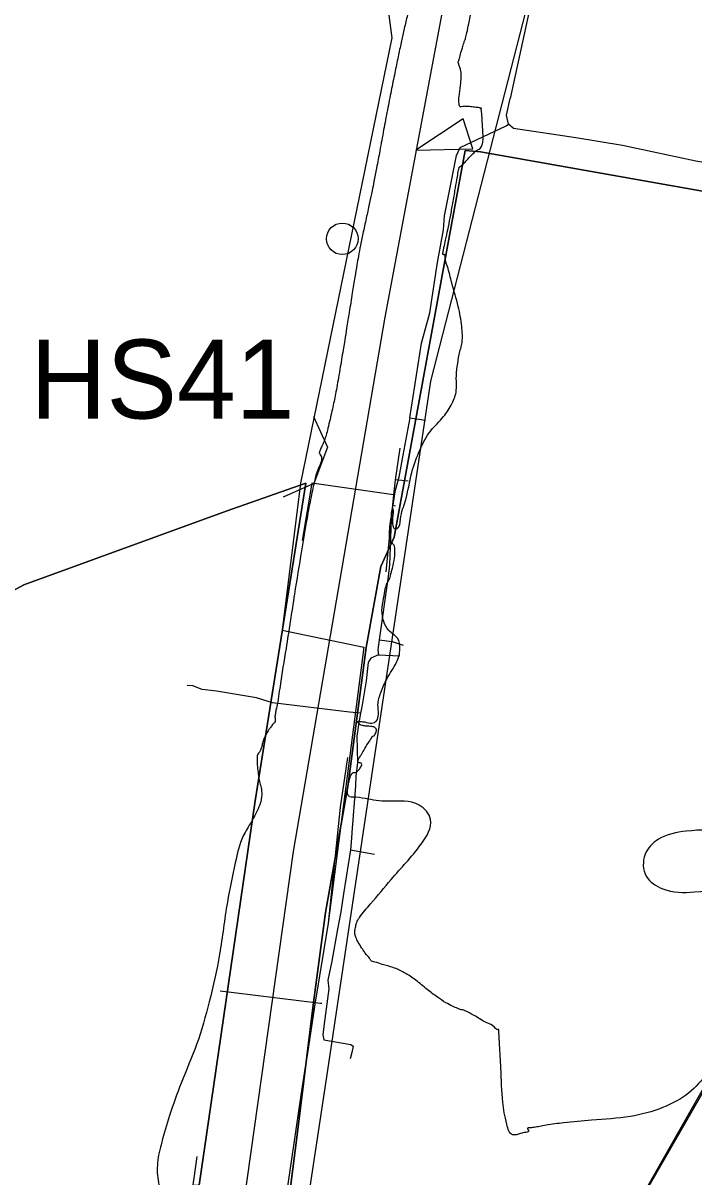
# Model space of a CAD drawing. Extents: x -478232 to -472707, y -1118753 to -1113967.
# Drawn here: x -475972.9 to -475887.9, y -1117588.2 to -1117442 of the extents above; entities that cross this region are included whole.
import ezdxf

# ---------------------------------------------------------------- set-up
doc = ezdxf.new("R2010")
doc.units = 0
for name, color, linetype in [('cesty', 7, 'Continuous'), ('hospodářské sjezdy', 7, 'Continuous'), ('nesmenovane pozemky', 7, 'Continuous'), ('ObPÚ', 7, 'Continuous'), ('plyn_stl', 7, 'Continuous'), ('silnice', 7, 'Continuous'), ('telekomunikační kabel_O2', 7, 'Continuous'), ('VAK_vodovod', 7, 'Continuous'), ('Vrstevnice_vedlejsi', 7, 'Continuous')]:
    doc.layers.add(name, color=color, linetype=linetype)

msp = doc.modelspace()

# ---------------------------------------------------------------- linework, layer by layer
at = {"layer": 'cesty'}
msp.add_line((-475915.938, -1117457.98), (-475917.133, -1117454.162), dxfattribs=at)
msp.add_lwpolyline([(-475917.133, -1117454.162), (-475923.164, -1117458.147), (-475915.938, -1117457.98)], dxfattribs=at)
msp.add_circle((-475932.467, -1117469.362), 2, dxfattribs=at)
at = {"layer": 'hospodářské sjezdy'}
for p, q in [((-475936.094, -1117491.874), (-475934.346, -1117495.765)), ((-475934.346, -1117495.765), (-475936.078, -1117500.333)), ((-475936.078, -1117500.333), (-475939.967, -1117502.085))]:
    msp.add_line(p, q, dxfattribs=at)
at = {"layer": 'nesmenovane pozemky'}
for p, q in [((-475916.88, -1117458.16), (-475919.49, -1117472.13)), ((-475919.49, -1117472.13), (-475925.88, -1117507.14)), ((-475934.6, -1117554.69), (-475936.13, -1117566.09))]:
    msp.add_line(p, q, dxfattribs=at)
for points in [[(-475951.7, -1117685.1), (-475927.26, -1117688.72), (-475918.95, -1117689.8), (-475884.78, -1117695.44), (-475871.68, -1117697.52), (-475898.5, -1117669.12), (-475903.93, -1117664.35), (-475905.71, -1117629.13), (-475906.78, -1117612.16), (-475902.49, -1117604.75), (-475882.63, -1117570.25), (-475876.2, -1117558.77), (-475871.25, -1117549.71), (-475870.12, -1117548.49), (-475868.56, -1117541.56), (-475866.64, -1117537.01), (-475865.5, -1117532.56), (-475858.35, -1117525.46), (-475844.8, -1117506.28), (-475833.86, -1117486.94), (-475831.88, -1117483.59), (-475829.4, -1117473.48), (-475914.94, -1117458.35), (-475916.88, -1117458.16)], [(-475919.49, -1117472.13), (-475916.88, -1117458.16), (-475914.94, -1117458.35), (-475829.4, -1117473.48), (-475831.88, -1117483.59), (-475833.86, -1117486.94), (-475844.8, -1117506.28), (-475858.35, -1117525.46), (-475865.5, -1117532.56), (-475866.64, -1117537.01), (-475868.56, -1117541.56), (-475870.12, -1117548.49), (-475871.25, -1117549.71), (-475876.2, -1117558.77), (-475882.63, -1117570.25), (-475902.49, -1117604.75)], [(-475940.34, -1117599.73), (-475938.19, -1117582.83), (-475936.13, -1117566.09), (-475934.6, -1117554.69), (-475931.78, -1117538.72), (-475929.43, -1117521.14), (-475927.57, -1117510.84), (-475925.88, -1117507.14), (-475919.49, -1117472.13)], [(-475937.08, -1117500.29), (-475943.5, -1117540.53), (-475950.59, -1117589.22), (-475972.84, -1117590.29), (-476004.64, -1117592.26), (-475999.55, -1117575.26), (-475994.23, -1117573.44), (-475992.2, -1117563.25), (-475986.19, -1117534.11), (-475984.93, -1117525.82), (-475982.04, -1117518.19), (-475972.81, -1117513.2), (-475947.17, -1117503.84), (-475937.08, -1117500.29)], [(-475947.17, -1117503.84), (-475972.81, -1117513.2), (-475982.04, -1117518.19), (-475984.93, -1117525.82), (-475986.19, -1117534.11), (-475992.2, -1117563.25), (-475994.23, -1117573.44), (-475999.55, -1117575.26), (-476004.64, -1117592.26), (-475972.84, -1117590.29), (-475950.59, -1117589.22), (-475943.5, -1117540.53), (-475937.08, -1117500.29), (-475947.17, -1117503.84)], [(-475925.88, -1117507.14), (-475927.57, -1117510.84), (-475929.43, -1117521.14), (-475931.78, -1117538.72), (-475934.6, -1117554.69)], [(-475936.13, -1117566.09), (-475938.19, -1117582.83), (-475940.34, -1117599.73)]]:
    msp.add_lwpolyline(points, dxfattribs=at)
at = {"layer": 'ObPÚ'}
msp.add_lwpolyline([(-475797.1, -1117434.24), (-475812.51, -1117451.24), (-475815.72, -1117464.29), (-475829.4, -1117473.48), (-475831.88, -1117483.59), (-475844.8, -1117506.28), (-475858.35, -1117525.46), (-475865.5, -1117532.56), (-475866.64, -1117537.01), (-475868.56, -1117541.56), (-475870.12, -1117548.49), (-475871.25, -1117549.71), (-475906.78, -1117612.16), (-475903.93, -1117664.35), (-475871.68, -1117697.52), (-475884.78, -1117695.44), (-475927.26, -1117688.72), (-475927.26, -1117688.72), (-475951.7, -1117685.1), (-475955.15, -1117684.42), (-475964.23, -1117682.64), (-475976.69, -1117679.99)], dxfattribs=at)
at = {"layer": 'plyn_stl'}
for p, q in [((-475925.98, -1117501.775), (-475926.943, -1117511.519)), ((-475947.94, -1117564.611), (-475946.213, -1117564.822)), ((-475946.213, -1117564.822), (-475935.234, -1117566.161)), ((-475935.234, -1117566.161), (-475935.062, -1117566.182))]:
    msp.add_line(p, q, dxfattribs=at)
for points in [[(-475925.179, -1117495.887), (-475925.776, -1117499.864), (-475925.98, -1117501.775), (-475927.156, -1117501.607), (-475936.338, -1117500.287), (-475937.535, -1117507.551)], [(-475924.115, -1117500.041), (-475924.12, -1117500.04), (-475924.5, -1117500), (-475925.776, -1117499.864)], [(-475950.891, -1117585.581), (-475951.277, -1117588.32), (-475951.277, -1117588.32), (-475952.244, -1117594.708), (-475952.569, -1117598.534), (-475951.885, -1117598.735), (-475939.635, -1117602.325), (-475939.681, -1117602.62), (-475941.682, -1117615.413), (-475944.166, -1117633.413), (-475944.166, -1117633.413), (-475944.769, -1117640.016), (-475945.933, -1117645.497), (-475946.953, -1117652.292), (-475950.061, -1117674.019), (-475950.384, -1117679.114), (-475952.306, -1117682.652), (-475953.329, -1117685.537), (-475953.931, -1117690.234), (-475955.586, -1117703.027), (-475955.894, -1117706.481)]]:
    msp.add_lwpolyline(points, dxfattribs=at)
at = {"layer": 'silnice'}
msp.add_lwpolyline([(-475957.898, -1117684.778), (-475949.882, -1117626.621), (-475938.626, -1117546.976), (-475927.029, -1117479.269), (-475917.649, -1117429.299), (-475903.982, -1117378.322)], dxfattribs=at)
at = {"layer": 'telekomunikační kabel_O2'}
for points in [[(-475967.4, -1117098.97), (-475940.43, -1117167.78), (-475950.06, -1117174), (-475931.33, -1117228.82), (-475924.1, -1117281.32), (-475911.23, -1117358.65), (-475927.92, -1117430.83), (-475926.17, -1117443.9), (-475937.75, -1117500.32), (-475940.1, -1117518.94), (-475929.72, -1117521.06), (-475934.27, -1117556.02), (-475935.89, -1117566.02), (-475936.969, -1117573.032)], [(-475891.45, -1117356.54), (-475891.64, -1117357.2), (-475890.45, -1117362.41), (-475889.23, -1117368.48), (-475890.21, -1117370.93), (-475900.63, -1117410.24), (-475907.44, -1117434.27), (-475911.21, -1117451.58)], [(-475911.41, -1117454.83), (-475911.67, -1117453.71), (-475911.21, -1117451.58)], [(-475923.91, -1117492.02), (-475922.43, -1117482.59), (-475921.39, -1117478.74), (-475920.39, -1117472.37), (-475919.64, -1117468.22), (-475919.5, -1117466.47), (-475918.95, -1117463.72), (-475918, -1117458.79), (-475917.51, -1117457.78), (-475911.68, -1117455.04), (-475911.41, -1117454.83)], [(-475866.596, -1117463.609), (-475871.46, -1117462.74), (-475878.05, -1117461.1), (-475887.67, -1117459.53), (-475896.96, -1117457.53), (-475902.86, -1117456.57), (-475910.78, -1117455.39), (-475911.41, -1117454.83)], [(-475923.91, -1117492.02), (-475924.79, -1117496.76), (-475925.31, -1117499.54), (-475925.81, -1117501.42), (-475926.04, -1117503.08)], [(-475923.91, -1117492.02), (-475921.9, -1117492.32)], [(-475926.04, -1117503.08), (-475926.26, -1117504.12), (-475926.26, -1117504.92), (-475926.36, -1117507.25), (-475926.48, -1117510.66), (-475926.65, -1117512.14), (-475927.78, -1117520.16)], [(-475926.04, -1117503.08), (-475925.78, -1117503.17)], [(-475927.78, -1117520.16), (-475927.97, -1117521.4), (-475927.89, -1117522.04)], [(-475927.78, -1117520.16), (-475926.14, -1117520.38), (-475924.73, -1117520.81)], [(-475927.89, -1117522.04), (-475928.86, -1117522.49), (-475929.19, -1117523.03), (-475929.45, -1117525.32), (-475929.97, -1117528.65), (-475930.16, -1117529.45)], [(-475927.89, -1117522.04), (-475925.19, -1117522.16)], [(-475930.16, -1117529.45), (-475931.57, -1117529.33), (-475941.31, -1117528.12), (-475943.33, -1117527.48), (-475948.39, -1117526.66), (-475950.2, -1117526.42), (-475951.4, -1117525.97), (-475952.12, -1117525.92)], [(-475930.16, -1117529.45), (-475930.43, -1117530.9), (-475930.6, -1117532.33), (-475930.55, -1117535.71), (-475930.75, -1117537.38), (-475930.78, -1117538.62), (-475931.26, -1117544.56), (-475931.29, -1117545.26), (-475931.44, -1117546.73)], [(-475931.82, -1117535.04), (-475932.74, -1117541.33), (-475934.27, -1117556.02), (-475935.89, -1117566.02), (-475937.71, -1117577.81), (-475938.91, -1117585.91), (-475941.61, -1117604.26), (-475944.33, -1117624.51)], [(-475931.44, -1117546.73), (-475932.33, -1117552.33), (-475932.65, -1117554.6), (-475933.06, -1117556.79), (-475933.78, -1117560.85), (-475934.28, -1117563.23), (-475934.17, -1117564.33), (-475934.76, -1117568.78), (-475934.91, -1117570.19), (-475934.8, -1117570.81), (-475931.38, -1117571.38), (-475931.07, -1117571.61), (-475931.27, -1117572.4), (-475931.48, -1117573.22)], [(-475931.44, -1117546.73), (-475928.4, -1117547.31)]]:
    msp.add_lwpolyline(points, dxfattribs=at)
at = {"layer": 'VAK_vodovod'}
msp.add_lwpolyline([(-475961.022, -1117076.006), (-475947.88, -1117107.78), (-475947.26, -1117108.989), (-475886.863, -1117255.251), (-475879.338, -1117287.714), (-475878.218, -1117296.341), (-475877.862, -1117316.562), (-475878.829, -1117320.819), (-475879.236, -1117324.31), (-475879.403, -1117324.54), (-475921.268, -1117487.378), (-475934.347, -1117574.649), (-475937.667, -1117596.666), (-475938.465, -1117600.746), (-475938.582, -1117601.233), (-475938.757, -1117601.897), (-475940.979, -1117601.583)], dxfattribs=at)
at = {"layer": 'Vrstevnice_vedlejsi'}
for points in [[(-475916.975, -1117444.292), (-475916.91, -1117444.15), (-475916.838, -1117443.929), (-475916.758, -1117443.629), (-475916.67, -1117443.25), (-475916.443, -1117442.153), (-475916.077, -1117440.337), (-475915.571, -1117437.802), (-475915.215, -1117436.045), (-475915.01, -1117435.066), (-475914.956, -1117434.864), (-475914.76, -1117434.04), (-475914.422, -1117432.594), (-475913.943, -1117430.524), (-475913.61, -1117429.082), (-475913.424, -1117428.266), (-475913.385, -1117428.077), (-475913.184, -1117427.193), (-475912.819, -1117425.614), (-475912.291, -1117423.339), (-475911.931, -1117421.787), (-475911.737, -1117420.958), (-475911.711, -1117420.852), (-475911.47, -1117419.881), (-475911.014, -1117418.045), (-475910.343, -1117415.344), (-475909.896, -1117413.541), (-475909.671, -1117412.636), (-475909.669, -1117412.628), (-475909.667, -1117412.619), (-475909.664, -1117412.607), (-475909.661, -1117412.594), (-475909.477, -1117411.965), (-475909.111, -1117410.721), (-475908.564, -1117408.862), (-475908.198, -1117407.614), (-475908.011, -1117406.977), (-475908.005, -1117406.952), (-475908, -1117406.932), (-475907.996, -1117406.917), (-475907.995, -1117406.907), (-475907.754, -1117405.931), (-475907.275, -1117403.988), (-475906.557, -1117401.079), (-475905.997, -1117398.788), (-475905.596, -1117397.117), (-475905.352, -1117396.064), (-475905.125, -1117395.027), (-475904.914, -1117394.006), (-475904.721, -1117393.002), (-475904.431, -1117391.559), (-475904.045, -1117389.677), (-475903.563, -1117387.357), (-475903.25, -1117385.773), (-475903.106, -1117384.926), (-475903.131, -1117384.815), (-475903.261, -1117384.756), (-475903.497, -1117384.749), (-475903.839, -1117384.794), (-475904.936, -1117385.955), (-475906.789, -1117388.231), (-475909.397, -1117391.622), (-475911.147, -1117393.894), (-475912.039, -1117395.047), (-475912.072, -1117395.08), (-475912.108, -1117395.141), (-475912.145, -1117395.227), (-475912.185, -1117395.34), (-475912.276, -1117395.491), (-475912.417, -1117395.68), (-475912.611, -1117395.908), (-475913.012, -1117397.232), (-475913.622, -1117399.653), (-475914.441, -1117403.172), (-475915.248, -1117406.458), (-475916.043, -1117409.512), (-475916.828, -1117412.333), (-475917.46, -1117414.614), (-475917.94, -1117416.353), (-475918.268, -1117417.552), (-475918.666, -1117419.012), (-475919.134, -1117420.732), (-475919.673, -1117422.713), (-475920.196, -1117424.706), (-475920.704, -1117426.711), (-475921.195, -1117428.727), (-475921.645, -1117430.593), (-475922.054, -1117432.306), (-475922.421, -1117433.869), (-475922.836, -1117435.571), (-475923.299, -1117437.415), (-475923.809, -1117439.399), (-475924.263, -1117441.241), (-475924.661, -1117442.942), (-475925.002, -1117444.501), (-475925.384, -1117446.3), (-475925.807, -1117448.34)], [(-475926.806, -1117512.989), (-475926.594, -1117512.679), (-475926.364, -1117512.04), (-475926.115, -1117511.073), (-475925.848, -1117509.779), (-475925.79, -1117508.798), (-475925.942, -1117508.13), (-475926.304, -1117507.777), (-475926.467, -1117507.007), (-475926.43, -1117505.822), (-475926.193, -1117504.22), (-475926.061, -1117503.535), (-475926.032, -1117503.767), (-475926.107, -1117504.915), (-475926.054, -1117505.677), (-475925.872, -1117506.054), (-475925.562, -1117506.044), (-475925.091, -1117504.861), (-475924.459, -1117502.506), (-475923.667, -1117498.977), (-475922.599, -1117496.031), (-475921.256, -1117493.667), (-475919.639, -1117491.885), (-475918.56, -1117490.191), (-475918.018, -1117488.587), (-475918.015, -1117487.071), (-475917.893, -1117485.547), (-475917.653, -1117484.016), (-475917.295, -1117482.477), (-475917.333, -1117480.451), (-475917.767, -1117477.938), (-475918.596, -1117474.938), (-475919.15, -1117472.871), (-475919.428, -1117471.736), (-475919.431, -1117471.534), (-475919.47, -1117471.408), (-475919.543, -1117471.356), (-475919.652, -1117471.379), (-475919.714, -1117471.331), (-475919.728, -1117471.212), (-475919.695, -1117471.021), (-475919.578, -1117470.457), (-475919.377, -1117469.521), (-475919.091, -1117468.211), (-475918.797, -1117466.73), (-475918.495, -1117465.079), (-475918.184, -1117463.257), (-475917.954, -1117461.912), (-475917.804, -1117461.044), (-475917.736, -1117460.653), (-475917.673, -1117460.385), (-475917.615, -1117460.241), (-475917.563, -1117460.221), (-475917.503, -1117460.188), (-475917.434, -1117460.142), (-475917.357, -1117460.084), (-475917.117, -1117459.844), (-475916.715, -1117459.423), (-475916.15, -1117458.821), (-475915.694, -1117458.384), (-475915.347, -1117458.112), (-475915.11, -1117458.006), (-475914.917, -1117457.811), (-475914.77, -1117457.525), (-475914.668, -1117457.15), (-475914.632, -1117456.464), (-475914.662, -1117455.467), (-475914.757, -1117454.161), (-475914.82, -1117453.286), (-475914.849, -1117452.843), (-475914.845, -1117452.831), (-475914.844, -1117452.821), (-475914.845, -1117452.811), (-475914.848, -1117452.803), (-475914.854, -1117452.799), (-475914.862, -1117452.799), (-475914.872, -1117452.802), (-475915.096, -1117452.775), (-475915.535, -1117452.719), (-475916.188, -1117452.632), (-475916.735, -1117452.594), (-475917.175, -1117452.603), (-475917.509, -1117452.66), (-475917.671, -1117452.239), (-475917.659, -1117451.338), (-475917.476, -1117449.959), (-475917.402, -1117448.881), (-475917.44, -1117448.105), (-475917.587, -1117447.631), (-475917.691, -1117447.306), (-475917.752, -1117447.131), (-475917.769, -1117447.105), (-475917.697, -1117446.794), (-475917.537, -1117446.198), (-475917.288, -1117445.316), (-475917.101, -1117444.68), (-475916.975, -1117444.292)], [(-475925.807, -1117448.34), (-475926.271, -1117450.621), (-475926.743, -1117453.028), (-475927.223, -1117455.562), (-475927.71, -1117458.222), (-475928.119, -1117460.397), (-475928.448, -1117462.085), (-475928.698, -1117463.287), (-475929.008, -1117464.755), (-475929.377, -1117466.489), (-475929.805, -1117468.489), (-475930.153, -1117470.183), (-475930.42, -1117471.572), (-475930.607, -1117472.656), (-475930.864, -1117474.203), (-475931.192, -1117476.212), (-475931.591, -1117478.685), (-475931.911, -1117480.673), (-475932.154, -1117482.178), (-475932.319, -1117483.199), (-475932.507, -1117484.336), (-475932.716, -1117485.589), (-475932.947, -1117486.958), (-475933.165, -1117488.181), (-475933.369, -1117489.257), (-475933.56, -1117490.186), (-475933.776, -1117491.179), (-475934.018, -1117492.236), (-475934.284, -1117493.357), (-475934.519, -1117494.236), (-475934.723, -1117494.873), (-475934.895, -1117495.268), (-475935.041, -1117495.607), (-475935.161, -1117495.889), (-475935.254, -1117496.115), (-475935.322, -1117496.274), (-475935.366, -1117496.367), (-475935.386, -1117496.394), (-475935.348, -1117496.507), (-475935.253, -1117496.706), (-475935.101, -1117496.991), (-475935.105, -1117497.404), (-475935.264, -1117497.944), (-475935.579, -1117498.612), (-475935.962, -1117499.972), (-475936.413, -1117502.024), (-475936.932, -1117504.768), (-475937.635, -1117508.885), (-475938.521, -1117514.375), (-475939.592, -1117521.239), (-475940.344, -1117525.997), (-475940.776, -1117528.651), (-475940.89, -1117529.2), (-475940.962, -1117529.609), (-475940.994, -1117529.877), (-475940.984, -1117530.005), (-475940.975, -1117530.143), (-475940.967, -1117530.29), (-475940.96, -1117530.446), (-475940.993, -1117530.576), (-475941.066, -1117530.679), (-475941.18, -1117530.754), (-475941.378, -1117530.99), (-475941.658, -1117531.386), (-475942.021, -1117531.943), (-475942.311, -1117532.508), (-475942.528, -1117533.081), (-475942.672, -1117533.663), (-475942.827, -1117534.113), (-475942.993, -1117534.43), (-475943.171, -1117534.615), (-475943.259, -1117535.054), (-475943.258, -1117535.746), (-475943.166, -1117536.692), (-475943.05, -1117537.531), (-475942.909, -1117538.261), (-475942.742, -1117538.884), (-475942.673, -1117539.509), (-475942.701, -1117540.138), (-475942.826, -1117540.769), (-475943.252, -1117541.788), (-475943.979, -1117543.194), (-475945.007, -1117544.986), (-475946.021, -1117548.378), (-475947.023, -1117553.369), (-475948.011, -1117559.959), (-475949.315, -1117565.973), (-475950.935, -1117571.413), (-475952.871, -1117576.278), (-475954.339, -1117580.395), (-475955.339, -1117583.764), (-475955.87, -1117586.385), (-475955.761, -1117588.893), (-475955.011, -1117591.286), (-475953.62, -1117593.565), (-475952.783, -1117595.731), (-475952.5, -1117597.782)], [(-475917.209, -1117566.997), (-475917.413, -1117566.999), (-475917.838, -1117566.85), (-475918.484, -1117566.55), (-475919.352, -1117566.1), (-475920.421, -1117565.397), (-475921.69, -1117564.443), (-475923.161, -1117563.237), (-475924.603, -1117562.304), (-475926.015, -1117561.646), (-475927.397, -1117561.261), (-475928.341, -1117560.961), (-475928.845, -1117560.747), (-475928.911, -1117560.617), (-475929.032, -1117560.447), (-475929.209, -1117560.235), (-475929.442, -1117559.984), (-475929.74, -1117559.574), (-475930.103, -1117559.008), (-475930.53, -1117558.283), (-475930.791, -1117557.665), (-475930.885, -1117557.153), (-475930.813, -1117556.748), (-475930.761, -1117556.441), (-475930.728, -1117556.235), (-475930.715, -1117556.128), (-475930.636, -1117555.937), (-475930.491, -1117555.662), (-475930.279, -1117555.304), (-475928.872, -1117553.578), (-475926.271, -1117550.484), (-475922.475, -1117546.022), (-475921.285, -1117542.888), (-475922.703, -1117541.08), (-475926.727, -1117540.6), (-475929.539, -1117540.262), (-475931.141, -1117540.067), (-475931.531, -1117540.015), (-475931.757, -1117539.753), (-475931.82, -1117539.281), (-475931.719, -1117538.6), (-475931.605, -1117538.034), (-475931.479, -1117537.582), (-475931.34, -1117537.244), (-475931.183, -1117537.027), (-475931.008, -1117536.932), (-475930.816, -1117536.958), (-475930.6, -1117536.85), (-475930.362, -1117536.608), (-475930.1, -1117536.232), (-475930.002, -1117535.958), (-475930.069, -1117535.784), (-475930.299, -1117535.712), (-475930.449, -1117535.66), (-475930.518, -1117535.629), (-475930.507, -1117535.619), (-475930.497, -1117535.589), (-475930.488, -1117535.539), (-475930.48, -1117535.469), (-475930.458, -1117535.388), (-475930.42, -1117535.296), (-475930.366, -1117535.192), (-475930.143, -1117534.813), (-475929.751, -1117534.159), (-475929.188, -1117533.23), (-475928.781, -1117532.611), (-475928.528, -1117532.302), (-475928.43, -1117532.303), (-475928.33, -1117532.18), (-475928.228, -1117531.932), (-475928.124, -1117531.56), (-475928.283, -1117531.293), (-475928.707, -1117531.132), (-475929.394, -1117531.077), (-475929.9, -1117530.997), (-475930.223, -1117530.891), (-475930.365, -1117530.76), (-475930.455, -1117530.646), (-475930.495, -1117530.551), (-475930.484, -1117530.473), (-475930.182, -1117530.473), (-475929.588, -1117530.55), (-475928.702, -1117530.705), (-475928.133, -1117530.394), (-475927.88, -1117529.619), (-475927.943, -1117528.378), (-475927.584, -1117526.86), (-475926.801, -1117525.067), (-475925.595, -1117522.997), (-475925.153, -1117521.293), (-475925.474, -1117519.954), (-475926.559, -1117518.981), (-475927.212, -1117517.81), (-475927.435, -1117516.439), (-475927.226, -1117514.869), (-475927.016, -1117513.719), (-475926.806, -1117512.989)], [(-475877.52, -1117543.926), (-475877.604, -1117543.962), (-475877.689, -1117543.993), (-475877.775, -1117544.021), (-475877.862, -1117544.045), (-475877.948, -1117544.06), (-475878.032, -1117544.067), (-475878.116, -1117544.066), (-475879.954, -1117544.117), (-475883.546, -1117544.221), (-475888.893, -1117544.379), (-475892.41, -1117545.409), (-475894.095, -1117547.313), (-475893.949, -1117550.091), (-475891.857, -1117551.681), (-475887.82, -1117552.084), (-475881.837, -1117551.3), (-475877.783, -1117551.317), (-475875.659, -1117552.136), (-475875.464, -1117553.757), (-475875.382, -1117554.938), (-475875.411, -1117555.68), (-475875.552, -1117555.983), (-475876.087, -1117557.12), (-475877.015, -1117559.091), (-475878.337, -1117561.896), (-475879.605, -1117564.421), (-475880.82, -1117566.665), (-475881.983, -1117568.628), (-475883.168, -1117569.918), (-475884.374, -1117570.535), (-475885.603, -1117570.478), (-475886.113, -1117570.566), (-475885.904, -1117570.799), (-475884.976, -1117571.176), (-475884.277, -1117571.434), (-475883.805, -1117571.571), (-475883.562, -1117571.589), (-475883.372, -1117571.546), (-475883.234, -1117571.443), (-475883.148, -1117571.279), (-475883.059, -1117571.152), (-475882.964, -1117571.062), (-475882.866, -1117571.008), (-475882.827, -1117571.02), (-475882.848, -1117571.098), (-475882.928, -1117571.243), (-475883.026, -1117571.423), (-475883.14, -1117571.64), (-475883.272, -1117571.892), (-475883.39, -1117572.103), (-475883.494, -1117572.274), (-475883.585, -1117572.403), (-475884.466, -1117573.326), (-475886.138, -1117575.043), (-475888.6, -1117577.554), (-475891.876, -1117579.379), (-475895.966, -1117580.517), (-475900.871, -1117580.97), (-475904.427, -1117581.33), (-475906.634, -1117581.598), (-475907.493, -1117581.773), (-475908.147, -1117581.892), (-475908.598, -1117581.955), (-475908.845, -1117581.962), (-475908.983, -1117581.997), (-475909.013, -1117582.058), (-475908.934, -1117582.146), (-475908.886, -1117582.234), (-475908.872, -1117582.322), (-475908.889, -1117582.41), (-475909.23, -1117582.525), (-475909.895, -1117582.666), (-475910.884, -1117582.832), (-475911.626, -1117581.508), (-475912.121, -1117578.693), (-475912.369, -1117574.387), (-475912.536, -1117571.461), (-475912.622, -1117569.913), (-475912.626, -1117569.745), (-475912.628, -1117569.633), (-475912.629, -1117569.575), (-475912.628, -1117569.572), (-475912.626, -1117569.565), (-475912.623, -1117569.554), (-475912.62, -1117569.537), (-475912.626, -1117569.523), (-475912.64, -1117569.51), (-475912.664, -1117569.498), (-475912.681, -1117569.492), (-475912.691, -1117569.49), (-475912.695, -1117569.493), (-475913.176, -1117569.217), (-475914.134, -1117568.663), (-475915.57, -1117567.829), (-475916.595, -1117567.274), (-475917.209, -1117566.997)]]:
    msp.add_spline(points, degree=3, dxfattribs=at)

# ---------------------------------------------------------------- texts
at = {"layer": 'hospodářské sjezdy'}
msp.add_text('HS41', height=10, rotation=359.99999, dxfattribs=at).set_placement((-475971.988, -1117492.122))

doc.saveas('drawing.dxf')
